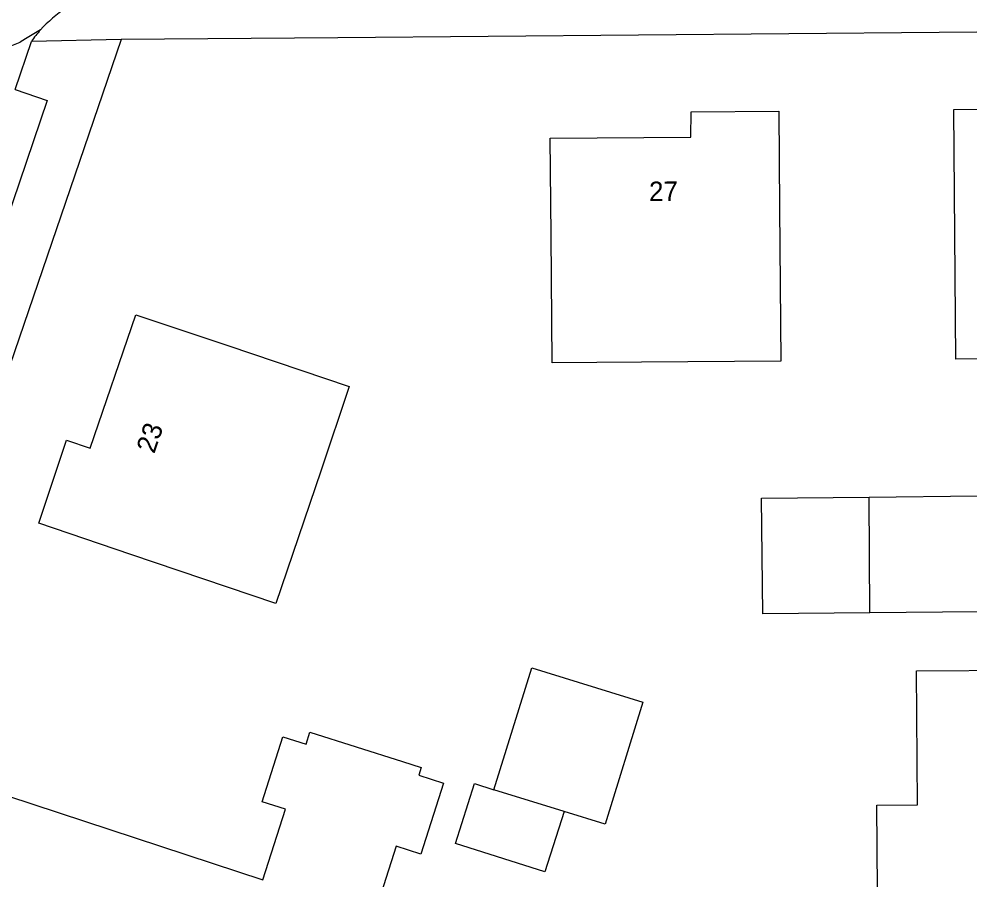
# Model space of a CAD drawing. Extents: x 157321 to 158827, y 386650 to 388532.
# Drawn here: x 157867.05 to 157916.06, y 387550.03 to 387594.4 of the extents above; entities that cross this region are included whole.
import ezdxf

# ---------------------------------------------------------------- set-up
doc = ezdxf.new("R2010")
doc.units = 0
for name, color, linetype in [('IMGEO_Pand', 7, 'Continuous'), ('IMGEO_Pand_nummerreeks', 7, 'Continuous'), ('IMGEO_Rijbaan_lokaal_gesloten', 7, 'Continuous'), ('IMGEO_Rijbaan_lokaal_open', 7, 'Continuous'), ('IMGEO_Voetpad_open', 7, 'Continuous')]:
    doc.layers.add(name, color=color, linetype=linetype)

msp = doc.modelspace()

# ---------------------------------------------------------------- linework, layer by layer
at = {"layer": 'IMGEO_Pand'}
for points in [[(157915.222, 387589.737), (157919.701, 387589.766), (157919.744, 387588.447), (157926.998, 387588.526), (157927.085, 387576.949), (157922.486, 387576.915), (157915.318, 387576.861), (157915.222, 387589.737)], [(157894.525, 387576.671), (157894.469, 387583.252), (157894.427, 387588.251), (157901.675, 387588.314), (157901.692, 387589.614), (157906.197, 387589.65), (157906.239, 387584.651), (157906.306, 387576.771), (157899.125, 387576.71), (157894.525, 387576.671)], [(157868.073, 387568.414), (157869.503, 387572.691), (157870.715, 387572.277), (157873.063, 387579.161), (157877.802, 387577.565), (157884.07, 387575.453), (157882.597, 387571.1), (157880.288, 387564.28), (157872.81, 387566.811), (157868.073, 387568.414)], [(157910.899, 387563.794), (157905.374, 387563.741), (157905.316, 387569.711), (157910.856, 387569.764)], [(157910.856, 387569.764), (157916.451, 387569.818), (157916.508, 387563.848), (157910.899, 387563.794)], [(157910.899, 387563.794), (157910.856, 387569.764)], [(157891.52, 387554.682), (157893.472, 387560.968), (157899.202, 387559.189), (157897.25, 387552.903), (157895.143, 387553.557)], [(157913.387, 387549.517), (157911.292, 387549.504), (157911.259, 387553.885), (157913.355, 387553.9), (157913.304, 387560.806), (157918.707, 387560.841), (157923.706, 387560.874), (157923.748, 387554.675), (157923.762, 387552.626), (157927.761, 387552.653), (157927.774, 387549.61), (157923.776, 387549.584)], [(157870.381, 387543.356), (157867.077, 387544.41), (157862.313, 387545.929), (157865.138, 387554.79), (157879.615, 387550.034), (157880.776, 387553.674), (157879.585, 387554.054), (157880.651, 387557.4), (157881.842, 387557.021), (157882.043, 387557.65), (157886.807, 387556.131), (157887.78, 387555.821), (157887.656, 387555.433), (157888.926, 387555.028), (157887.758, 387551.365), (157886.488, 387551.769), (157883.88, 387543.59), (157878.259, 387545.383), (157878.532, 387546.239), (157871.967, 387548.332), (157870.381, 387543.356)], [(157895.143, 387553.557), (157894.151, 387550.443), (157889.539, 387551.913), (157890.523, 387555), (157891.52, 387554.682)], [(157895.143, 387553.557), (157891.52, 387554.682)]]:
    msp.add_lwpolyline(points, dxfattribs=at)
at = {"layer": 'IMGEO_Rijbaan_lokaal_gesloten'}
for points in [[(157868.151, 387593.832), (157867.387, 387593.369), (157867.102, 387593.197)], [(157866.853, 387590.762), (157867.69, 387593.242)]]:
    msp.add_lwpolyline(points, dxfattribs=at)
for centre, radius, start, end in [((157872.099, 387590.272), 5.316, 137.959, 146.036), ((157859.781, 387611.181), 19.417, 270.6205, 292.1511)]:
    msp.add_arc(centre, radius, start, end, dxfattribs=at)
at = {"layer": 'IMGEO_Rijbaan_lokaal_open'}
msp.add_arc((157873.842, 387588.549), 7.765, 124.3098, 137.1294, dxfattribs=at)
at = {"layer": 'IMGEO_Voetpad_open'}
for points in [[(157929.973, 387592.849), (157929.964, 387593.836), (157883.473, 387593.43), (157872.307, 387593.332)], [(157872.307, 387593.332), (157854.157, 387540.227)], [(157872.307, 387593.332), (157867.69, 387593.242)], [(157866.853, 387590.762), (157868.504, 387590.193), (157861.356, 387569.162)]]:
    msp.add_lwpolyline(points, dxfattribs=at)

# ---------------------------------------------------------------- texts
at = {"layer": 'IMGEO_Pand_nummerreeks'}
for s, rotation, p in [('27', 0.498, (157899.52, 387585.015)), ('23', 71.1665, (157874.016, 387571.96))]:
    msp.add_text(s, height=1, rotation=rotation, dxfattribs=at).set_placement(p)

doc.saveas('drawing.dxf')
